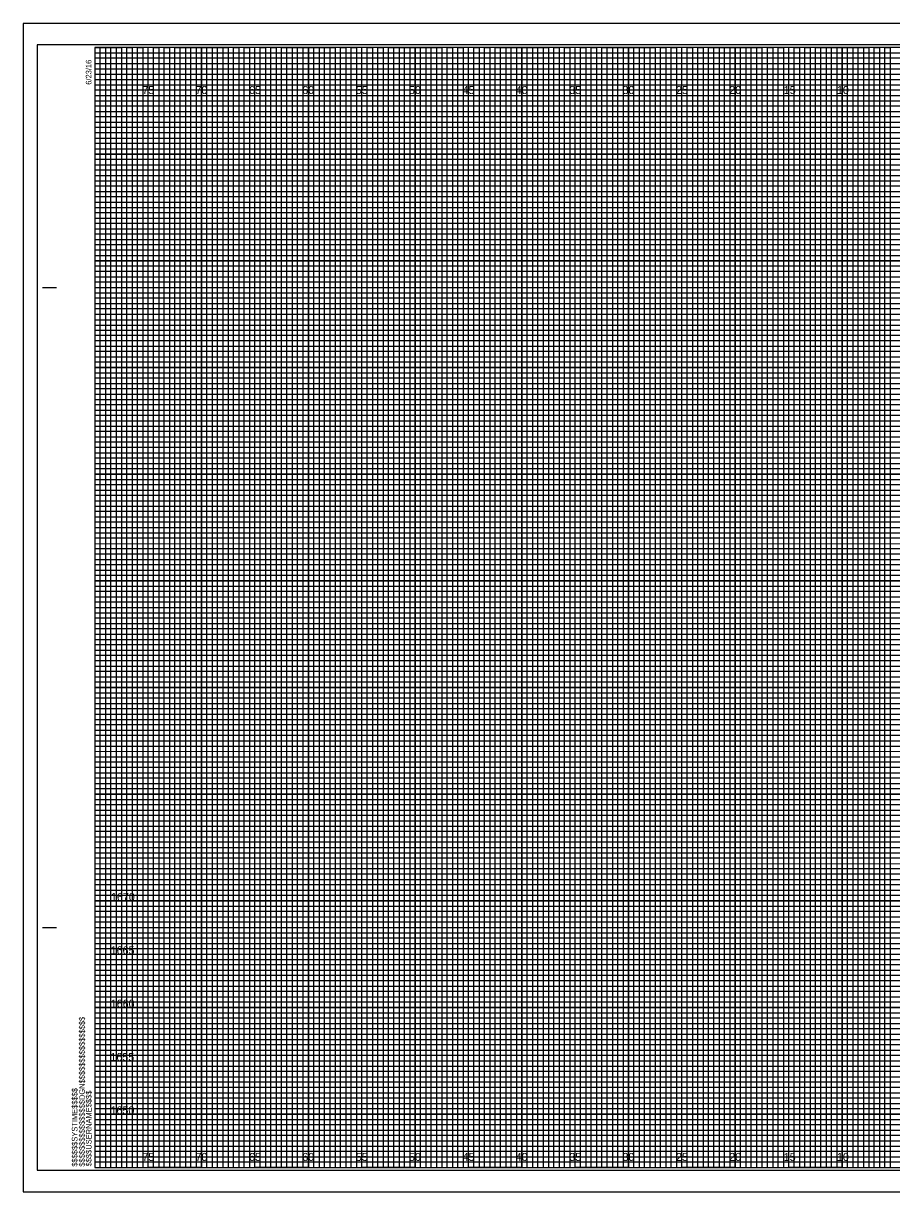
# Model space of a CAD drawing. Extents: x 224 to 392, y 1 to 330.
# Drawn here: x 223.6 to 304.9, y 221 to 330.5 of the extents above; entities that cross this region are included whole.
import ezdxf

# ---------------------------------------------------------------- set-up
doc = ezdxf.new("R2010")
doc.units = 0
for name, color, linetype in [('Prop Grid Mask', 7, 'Continuous'), ('Prop XS Elevation Labels', 7, 'Continuous'), ('Sheet Cross Section CELL', 7, 'Continuous'), ('Sheet Cross Section Grid Major CELL', 7, 'Continuous'), ('Sheet Cross Section Grid Middle CELL', 7, 'Continuous'), ('Sheet Cross Section Grid Minor 1 CELL', 7, 'Continuous'), ('Sheet Cross Section Grid Minor 2 CELL', 7, 'Continuous'), ('Sheet Cutting Line CELL', 7, 'Continuous'), ('Sheet DOT Grid CELL', 7, 'Continuous'), ('Sheet Plot Border Inside CELL', 7, 'Continuous'), ('Sheet Plot Border Outside CELL', 7, 'Continuous')]:
    doc.layers.add(name, color=color, linetype=linetype)

msp = doc.modelspace()

# ---------------------------------------------------------------- linework, layer by layer
at = {"layer": 'Sheet Cross Section CELL'}
for p, q in [((225.36, 305.71), (226.61, 305.71)), ((225.41, 305.71), (226.66, 305.71)), ((225.36, 245.71), (226.61, 245.71)), ((225.41, 245.71), (226.66, 245.71)), ((230.26, 223.21), (230.26, 223.21)), ((230.26, 223.21), (230.26, 223.21)), ((230.26, 223.21), (230.26, 223.21)), ((230.26, 223.21), (230.26, 223.21)), ((230.26, 223.21), (230.26, 223.21)), ((230.26, 223.21), (230.26, 223.21)), ((230.26, 223.21), (230.26, 223.21))]:
    msp.add_line(p, q, dxfattribs=at)
msp.add_lwpolyline([(390.26, 328.21), (230.26, 328.21), (230.26, 223.21), (390.26, 223.21)], close=True, dxfattribs=at)
at = {"layer": 'Sheet Cross Section Grid Major CELL'}
for p, q in [((235.26, 328.21), (230.26, 328.21)), ((235.26, 223.21), (235.26, 328.21)), ((245.26, 328.21), (240.26, 328.21)), ((240.26, 328.21), (240.26, 223.21)), ((245.26, 223.21), (245.26, 328.21)), ((255.26, 328.21), (250.26, 328.21)), ((250.26, 328.21), (250.26, 223.21)), ((255.26, 223.21), (255.26, 328.21)), ((265.26, 328.21), (260.26, 328.21)), ((260.26, 328.21), (260.26, 223.21)), ((265.26, 223.21), (265.26, 328.21)), ((275.26, 328.21), (270.26, 328.21)), ((270.26, 328.21), (270.26, 223.21)), ((275.26, 223.21), (275.26, 328.21)), ((285.26, 328.21), (280.26, 328.21)), ((280.26, 328.21), (280.26, 223.21)), ((285.26, 223.21), (285.26, 328.21)), ((295.26, 328.21), (290.26, 328.21)), ((290.26, 328.21), (290.26, 223.21)), ((295.26, 223.21), (295.26, 328.21)), ((305.26, 328.21), (300.26, 328.21)), ((300.26, 328.21), (300.26, 223.21)), ((240.26, 223.21), (235.26, 223.21)), ((250.26, 223.21), (245.26, 223.21)), ((260.26, 223.21), (255.26, 223.21)), ((270.26, 223.21), (265.26, 223.21)), ((280.26, 223.21), (275.26, 223.21)), ((290.26, 223.21), (285.26, 223.21)), ((300.26, 223.21), (295.26, 223.21))]:
    msp.add_line(p, q, dxfattribs=at)
for points in [[(230.26, 323.21), (390.26, 323.21), (390.26, 318.21), (230.26, 318.21)], [(230.26, 313.21), (390.26, 313.21), (390.26, 308.21), (230.26, 308.21)], [(230.26, 303.21), (390.26, 303.21), (390.26, 298.21), (230.26, 298.21)], [(230.26, 293.21), (390.26, 293.21), (390.26, 288.21), (230.26, 288.21)], [(230.26, 283.21), (390.26, 283.21), (390.26, 278.21), (230.26, 278.21)], [(230.26, 273.21), (390.26, 273.21), (390.26, 268.21), (230.26, 268.21)], [(230.26, 263.21), (390.26, 263.21), (390.26, 258.21), (230.26, 258.21)], [(230.26, 253.21), (390.26, 253.21), (390.26, 248.21), (230.26, 248.21)], [(230.26, 243.21), (390.26, 243.21), (390.26, 238.21), (230.26, 238.21)], [(230.26, 233.21), (390.26, 233.21), (390.26, 228.21), (230.26, 228.21)]]:
    msp.add_lwpolyline(points, dxfattribs=at)
at = {"layer": 'Sheet Cross Section Grid Middle CELL'}
for points in [[(230.26, 328.21), (232.76, 328.21), (232.76, 223.21), (237.76, 223.21), (237.76, 328.21), (242.76, 328.21), (242.76, 223.21), (247.76, 223.21), (247.76, 328.21), (252.76, 328.21), (252.76, 223.21), (257.76, 223.21), (257.76, 328.21), (262.76, 328.21), (262.76, 223.21), (267.76, 223.21), (267.76, 328.21), (272.76, 328.21), (272.76, 223.21), (277.76, 223.21), (277.76, 328.21), (282.76, 328.21), (282.76, 223.21), (287.76, 223.21), (287.76, 328.21), (292.76, 328.21), (292.76, 223.21), (297.76, 223.21), (297.76, 328.21), (302.76, 328.21), (302.76, 223.21), (307.76, 223.21)], [(230.26, 325.71), (367.76, 325.71)], [(230.26, 315.71), (390.26, 315.71), (390.26, 320.71), (230.26, 320.71)], [(230.26, 305.71), (390.26, 305.71), (390.26, 310.71), (230.26, 310.71)], [(230.26, 295.71), (390.26, 295.71), (390.26, 300.71), (230.26, 300.71)], [(230.26, 285.71), (390.26, 285.71), (390.26, 290.71), (230.26, 290.71)], [(230.26, 275.71), (390.26, 275.71), (390.26, 280.71), (230.26, 280.71)], [(230.26, 265.71), (390.26, 265.71), (390.26, 270.71), (230.26, 270.71)], [(230.26, 255.71), (390.26, 255.71), (390.26, 260.71), (230.26, 260.71)], [(230.26, 245.71), (390.26, 245.71), (390.26, 250.71), (230.26, 250.71)], [(230.26, 235.71), (390.26, 235.71), (390.26, 240.71), (230.26, 240.71)], [(230.26, 225.71), (390.26, 225.71), (390.26, 230.71), (230.26, 230.71)]]:
    msp.add_lwpolyline(points, dxfattribs=at)
at = {"layer": 'Sheet Cross Section Grid Minor 1 CELL'}
for p, q in [((230.26, 327.71), (360.26, 327.71)), ((360.26, 327.2), (230.26, 327.2)), ((230.26, 327.2), (230.26, 326.71)), ((230.26, 326.71), (360.26, 326.71)), ((360.26, 326.16), (230.26, 326.16)), ((230.26, 326.16), (230.26, 325.21)), ((230.26, 325.21), (390.26, 325.21))]:
    msp.add_line(p, q, dxfattribs=at)
for points in [[(230.26, 324.71), (365.26, 324.71), (390.26, 324.71), (390.26, 324.21), (230.26, 324.21)], [(230.26, 323.71), (390.26, 323.71), (390.26, 322.71), (230.26, 322.71)], [(230.26, 322.21), (390.26, 322.21), (390.26, 321.71), (230.26, 321.7)], [(230.26, 321.21), (390.26, 321.21), (390.26, 320.21), (230.26, 320.21)], [(230.26, 319.71), (390.26, 319.71), (390.26, 319.21), (230.26, 319.21)], [(230.26, 318.71), (390.26, 318.71), (390.26, 317.71), (230.26, 317.71)], [(230.26, 317.21), (390.26, 317.21), (390.26, 316.71), (230.26, 316.71)], [(230.26, 316.21), (390.26, 316.21), (390.26, 315.21), (230.26, 315.21)], [(230.26, 314.71), (390.26, 314.71), (390.26, 314.21), (230.26, 314.21)], [(230.26, 313.71), (390.26, 313.71), (390.26, 312.71), (230.26, 312.71)], [(230.26, 312.21), (390.26, 312.21), (390.26, 311.71), (230.26, 311.71)], [(230.26, 311.21), (390.26, 311.21), (390.26, 310.19), (390.26, 309.71), (390.26, 309.21), (230.26, 309.21)], [(230.26, 310.21), (390.26, 310.21), (390.26, 309.71), (230.26, 309.71)], [(230.26, 308.71), (390.26, 308.71), (390.26, 307.71), (230.26, 307.73)], [(230.26, 307.73), (390.26, 307.71), (390.26, 307.21), (230.26, 307.21)], [(230.26, 306.71), (390.26, 306.71), (390.26, 306.21), (230.26, 306.21)], [(230.26, 305.21), (390.26, 305.21), (390.26, 304.71), (230.26, 304.71)], [(230.26, 304.21), (390.26, 304.21), (390.26, 303.71), (230.26, 303.71)], [(230.23, 302.66), (390.26, 302.66), (390.26, 302.15), (230.23, 302.15)], [(230.26, 301.71), (390.26, 301.71), (390.26, 301.21), (230.26, 301.21)], [(230.26, 300.21), (390.26, 300.21), (390.26, 299.71), (230.26, 299.71)], [(230.26, 299.21), (390.26, 299.21), (390.26, 298.71), (230.26, 298.71)], [(230.26, 297.71), (390.26, 297.71), (390.26, 297.21), (230.26, 297.21)], [(230.26, 296.71), (390.26, 296.71), (390.26, 296.21), (230.26, 296.21)], [(230.26, 295.21), (390.26, 295.21), (390.26, 294.71), (230.26, 294.71)], [(230.26, 294.21), (390.26, 294.21), (390.26, 293.71), (230.26, 293.71)], [(230.26, 292.71), (390.26, 292.71), (390.26, 292.2), (230.26, 292.21)], [(230.26, 291.71), (390.26, 291.71), (390.26, 291.21), (230.26, 291.21)], [(230.26, 290.21), (390.26, 290.21), (390.26, 289.71), (230.26, 289.71)], [(230.26, 289.21), (390.26, 289.21), (390.26, 288.71), (230.26, 288.71)], [(230.26, 287.71), (390.26, 287.71), (390.26, 287.21), (230.26, 287.21)], [(230.26, 286.71), (390.26, 286.71), (390.26, 286.21), (230.26, 286.21)], [(230.26, 285.21), (390.26, 285.21), (390.26, 284.71), (230.26, 284.71)], [(230.26, 284.21), (390.26, 284.21), (390.26, 283.71), (230.26, 283.71)], [(230.26, 282.71), (390.26, 282.71), (390.26, 282.21), (230.26, 282.21)], [(230.26, 281.71), (390.3, 281.67), (390.26, 281.21), (230.26, 281.21)], [(230.26, 280.21), (390.26, 280.21), (390.26, 279.71), (230.26, 279.71)], [(230.26, 279.21), (390.26, 279.21), (390.26, 278.71), (230.26, 278.71)], [(230.26, 277.71), (390.26, 277.71), (390.26, 277.21), (230.26, 277.21)], [(230.26, 276.71), (390.26, 276.71), (390.26, 276.21), (230.26, 276.21)], [(230.26, 275.21), (390.26, 275.21), (390.26, 274.71), (230.26, 274.71)], [(230.26, 274.21), (390.26, 274.21), (390.26, 273.71), (230.26, 273.71)], [(230.26, 272.71), (390.26, 272.71), (390.26, 272.21), (230.26, 272.21)], [(230.26, 271.71), (390.26, 271.71), (390.26, 271.21), (230.26, 271.21)], [(230.26, 270.21), (390.26, 270.21), (390.26, 269.71), (230.26, 269.71)], [(230.26, 269.21), (390.26, 269.21), (390.26, 268.71), (230.26, 268.71)], [(230.26, 267.71), (390.26, 267.71), (390.26, 267.21), (230.26, 267.21)], [(230.26, 266.71), (390.26, 266.71), (390.26, 266.21), (230.26, 266.21)], [(230.26, 265.21), (390.26, 265.21), (390.26, 264.71), (230.26, 264.71)], [(230.26, 264.21), (390.26, 264.21), (390.26, 263.71), (230.26, 263.71)], [(230.26, 262.71), (390.26, 262.71), (390.26, 262.2), (230.26, 262.21)], [(230.26, 261.71), (390.26, 261.71), (390.26, 261.21), (230.26, 261.21)], [(230.26, 260.21), (390.26, 260.21), (390.26, 259.71), (230.26, 259.71)], [(230.26, 259.21), (390.26, 259.21), (390.26, 258.71), (230.26, 258.71)], [(230.26, 257.71), (390.26, 257.71), (390.26, 257.21), (230.26, 257.21)], [(230.26, 256.71), (390.26, 256.71), (390.26, 256.21), (230.26, 256.21)], [(230.26, 255.21), (390.26, 255.21), (390.26, 254.71), (230.26, 254.71)], [(230.26, 254.21), (390.26, 254.21), (390.26, 253.71), (230.26, 253.71)], [(230.26, 252.71), (390.26, 252.71), (390.26, 252.21), (230.26, 252.21)], [(230.26, 251.71), (390.3, 251.67), (390.26, 251.21), (230.26, 251.21)], [(230.26, 250.21), (390.26, 250.21), (390.26, 249.71), (230.26, 249.71)], [(230.26, 249.21), (390.26, 249.21), (390.26, 248.71), (230.26, 248.71)], [(230.26, 247.71), (390.26, 247.71), (390.26, 247.21), (230.26, 247.21)], [(230.26, 246.71), (390.26, 246.71), (390.26, 246.21), (230.26, 246.21)], [(230.26, 245.21), (390.26, 245.21), (390.26, 244.71), (230.26, 244.71)], [(230.26, 244.21), (390.26, 244.21), (390.26, 243.71), (230.26, 243.71)], [(230.26, 242.71), (390.26, 242.71), (390.26, 242.21), (230.26, 242.21)], [(230.26, 241.71), (390.26, 241.71), (390.26, 241.21), (230.26, 241.21)], [(230.26, 240.21), (390.26, 240.21), (390.26, 239.71), (230.26, 239.71)], [(230.26, 239.21), (390.26, 239.21), (390.26, 238.71), (230.26, 238.71)], [(230.26, 237.71), (390.26, 237.71), (390.26, 237.21), (230.26, 237.21)], [(230.26, 236.71), (390.26, 236.71), (390.26, 236.21), (230.26, 236.21)], [(230.26, 235.21), (390.26, 235.21), (390.26, 234.71), (230.26, 234.71)], [(230.26, 234.21), (390.26, 234.21), (390.26, 233.71), (230.26, 233.71)], [(230.26, 232.71), (390.26, 232.71), (390.26, 232.21), (230.26, 232.21)], [(230.26, 231.71), (390.26, 231.71), (390.26, 231.21), (230.26, 231.21)], [(230.26, 230.21), (390.26, 230.21), (390.26, 229.71), (230.26, 229.71)], [(230.26, 229.21), (390.26, 229.21), (390.26, 228.71), (230.26, 228.71)], [(230.26, 227.71), (390.26, 227.71), (390.26, 227.21), (230.26, 227.21)], [(230.26, 226.71), (390.26, 226.71), (390.26, 226.21), (230.26, 226.21)], [(230.26, 225.21), (390.26, 225.21), (390.26, 224.71), (230.26, 224.71)], [(230.26, 224.21), (390.26, 224.21), (390.26, 223.71), (230.26, 223.71)]]:
    msp.add_lwpolyline(points, dxfattribs=at)
at = {"layer": 'Sheet Cross Section Grid Minor 2 CELL'}
for points in [[(230.26, 223.21), (230.76, 223.21), (230.76, 328.21), (231.26, 328.21), (231.26, 223.21)], [(231.26, 223.21), (231.76, 223.21), (231.76, 328.21), (232.26, 328.21), (232.26, 223.21)], [(232.76, 223.21), (233.26, 223.21), (233.26, 328.21), (233.76, 328.21), (233.76, 223.21)], [(233.76, 223.21), (234.26, 223.21), (234.26, 328.21), (234.76, 328.21), (234.76, 223.21)], [(235.26, 223.21), (235.76, 223.21), (235.76, 328.21), (236.26, 328.21), (236.26, 223.21)], [(236.26, 223.21), (236.76, 223.21), (236.76, 328.21), (237.26, 328.21), (237.26, 223.21)], [(237.76, 223.21), (238.26, 223.21), (238.26, 328.21), (238.76, 328.21), (238.76, 223.21)], [(238.76, 223.21), (239.26, 223.21), (239.26, 328.21), (239.76, 328.21), (239.76, 223.21)], [(240.26, 223.21), (240.76, 223.21), (240.76, 328.21), (241.26, 328.21), (241.26, 223.21)], [(241.26, 223.21), (241.76, 223.21), (241.76, 328.21), (242.26, 328.21), (242.26, 223.21)], [(242.76, 223.21), (243.26, 223.21), (243.26, 328.21), (243.76, 328.21), (243.76, 223.21)], [(243.76, 223.21), (244.26, 223.21), (244.26, 328.21), (244.76, 328.21), (244.76, 223.21)], [(245.26, 223.21), (245.76, 223.21), (245.76, 328.21), (246.26, 328.21), (246.26, 223.21)], [(246.26, 223.21), (246.76, 223.21), (246.76, 328.21), (247.26, 328.21), (247.26, 223.21)], [(247.76, 223.21), (248.26, 223.21), (248.26, 328.21), (248.76, 328.21), (248.76, 223.21)], [(248.76, 223.21), (249.26, 223.21), (249.26, 328.21), (249.76, 328.21), (249.76, 223.21)], [(250.26, 223.21), (250.76, 223.21), (250.76, 328.21), (251.26, 328.21), (251.26, 223.21)], [(251.26, 223.21), (251.76, 223.21), (251.76, 328.21), (252.26, 328.21), (252.26, 223.21)], [(252.76, 223.21), (253.26, 223.21), (253.26, 328.21), (253.76, 328.21), (253.76, 223.21)], [(253.76, 223.21), (254.26, 223.21), (254.26, 328.21), (254.76, 328.21), (254.76, 223.21)], [(255.26, 223.21), (255.76, 223.21), (255.76, 328.21), (256.26, 328.21), (256.26, 223.21)], [(256.26, 223.21), (256.76, 223.21), (256.76, 328.21), (257.26, 328.21), (257.26, 223.21)], [(257.76, 223.21), (258.26, 223.21), (258.26, 328.21), (258.76, 328.21), (258.76, 223.21)], [(258.76, 223.21), (259.26, 223.21), (259.26, 328.21), (259.76, 328.21), (259.76, 223.21)], [(260.26, 223.21), (260.76, 223.21), (260.76, 328.21), (261.26, 328.21), (261.26, 223.21)], [(261.26, 223.21), (261.76, 223.21), (261.76, 328.21), (262.26, 328.21), (262.26, 223.21)], [(262.76, 223.21), (263.26, 223.21), (263.26, 328.21), (263.76, 328.21), (263.76, 223.21)], [(263.76, 223.21), (264.26, 223.21), (264.26, 328.21), (264.76, 328.21), (264.76, 223.21)], [(265.26, 223.21), (265.76, 223.21), (265.76, 328.21), (266.26, 328.21), (266.26, 223.21)], [(266.26, 223.21), (266.76, 223.21), (266.76, 328.21), (267.26, 328.21), (267.26, 223.21)], [(267.76, 223.21), (268.26, 223.21), (268.26, 328.21), (268.76, 328.21), (268.76, 223.21)], [(268.76, 223.21), (269.26, 223.21), (269.26, 328.21), (269.76, 328.21), (269.76, 223.21)], [(270.26, 223.21), (270.76, 223.21), (270.76, 328.21), (271.26, 328.21), (271.26, 223.21)], [(271.26, 223.21), (271.76, 223.21), (271.76, 328.21), (272.26, 328.21), (272.26, 223.21)], [(272.76, 223.21), (273.26, 223.21), (273.26, 328.21), (273.76, 328.21), (273.76, 223.21)], [(273.76, 223.21), (274.26, 223.21), (274.26, 328.21), (274.76, 328.21), (274.76, 223.21)], [(275.26, 223.21), (275.76, 223.21), (275.76, 328.21), (276.26, 328.21), (276.26, 223.21)], [(276.26, 223.21), (276.76, 223.21), (276.76, 328.21), (277.26, 328.21), (277.26, 223.21)], [(277.76, 223.21), (278.26, 223.21), (278.26, 328.21), (278.76, 328.21), (278.76, 223.21)], [(278.76, 223.21), (279.26, 223.21), (279.26, 328.21), (279.76, 328.21), (279.76, 223.21)], [(280.26, 223.21), (280.76, 223.21), (280.76, 328.21), (281.26, 328.21), (281.26, 223.21)], [(281.26, 223.21), (281.76, 223.21), (281.76, 328.21), (282.26, 328.21), (282.26, 223.21)], [(282.76, 223.21), (283.26, 223.21), (283.26, 328.21), (283.76, 328.21), (283.76, 223.21)], [(283.76, 223.21), (284.26, 223.21), (284.26, 328.21), (284.76, 328.21), (284.76, 223.21)], [(285.26, 223.21), (285.76, 223.21), (285.76, 328.21), (286.26, 328.21), (286.26, 223.21)], [(286.26, 223.21), (286.76, 223.21), (286.76, 328.21), (287.26, 328.21), (287.26, 223.21)], [(287.76, 223.21), (288.26, 223.21), (288.26, 328.21), (288.76, 328.21), (288.76, 223.21)], [(288.76, 223.21), (289.26, 223.21), (289.26, 328.21), (289.76, 328.21), (289.76, 223.21)], [(290.26, 223.21), (290.76, 223.21), (290.76, 328.21), (291.26, 328.21), (291.26, 223.21)], [(291.26, 223.21), (291.76, 223.21), (291.76, 328.21), (292.26, 328.21), (292.26, 223.21)], [(292.76, 223.21), (293.26, 223.21), (293.26, 328.21), (293.76, 328.21), (293.76, 223.21)], [(293.76, 223.21), (294.26, 223.21), (294.26, 328.21), (294.76, 328.21), (294.76, 223.21)], [(295.26, 223.21), (295.76, 223.21), (295.76, 328.21), (296.26, 328.21), (296.26, 223.21)], [(296.26, 223.21), (296.76, 223.21), (296.76, 328.21), (297.26, 328.21), (297.26, 223.21)], [(297.76, 223.21), (298.26, 223.21), (298.26, 328.21), (298.76, 328.21), (298.76, 223.21)], [(298.76, 223.21), (299.26, 223.21), (299.26, 328.21), (299.76, 328.21), (299.76, 223.21)], [(300.26, 223.21), (300.76, 223.21), (300.76, 328.21), (301.26, 328.21), (301.26, 223.21)], [(301.26, 223.21), (301.76, 223.21), (301.76, 328.21), (302.26, 328.21), (302.26, 223.21)], [(302.76, 223.21), (303.26, 223.21), (303.26, 328.21), (303.76, 328.21), (303.76, 223.21)], [(303.76, 223.21), (304.26, 223.21), (304.26, 328.21), (304.76, 328.21), (304.76, 223.21)]]:
    msp.add_lwpolyline(points, dxfattribs=at)
at = {"layer": 'Sheet Cutting Line CELL'}
for p, q in [((391.91, 330.46), (223.56, 330.46)), ((223.56, 330.46), (223.56, 220.96)), ((223.56, 220.96), (391.91, 220.96))]:
    msp.add_line(p, q, dxfattribs=at)
at = {"layer": 'Sheet DOT Grid CELL'}
for p, q in [((235.26, 223.21), (235.26, 328.21)), ((240.26, 223.21), (240.26, 328.21)), ((245.26, 223.21), (245.26, 328.21)), ((250.26, 223.21), (250.26, 328.21)), ((255.26, 223.21), (255.26, 328.21)), ((260.26, 223.21), (260.26, 328.21)), ((265.26, 223.21), (265.26, 328.21)), ((270.26, 223.21), (270.26, 328.21)), ((275.26, 223.21), (275.26, 328.21)), ((280.26, 223.21), (280.26, 328.21)), ((285.26, 223.21), (285.26, 328.21)), ((290.26, 223.21), (290.26, 328.21)), ((295.26, 223.21), (295.26, 328.21)), ((300.26, 223.21), (300.26, 328.21)), ((230.26, 323.21), (390.26, 323.21)), ((230.26, 318.21), (390.26, 318.21)), ((230.26, 313.21), (390.26, 313.21)), ((230.26, 308.21), (390.26, 308.21)), ((230.26, 303.21), (390.26, 303.21)), ((230.26, 298.21), (390.26, 298.21)), ((230.26, 293.21), (390.26, 293.21)), ((230.26, 288.21), (390.26, 288.21)), ((230.26, 283.21), (390.26, 283.21)), ((230.26, 278.21), (390.26, 278.21)), ((230.26, 273.21), (390.26, 273.21)), ((230.26, 268.21), (390.26, 268.21)), ((230.26, 263.21), (390.26, 263.21)), ((230.26, 258.21), (390.26, 258.21)), ((230.26, 253.21), (390.26, 253.21)), ((230.26, 248.21), (390.26, 248.21)), ((230.26, 243.21), (390.26, 243.21)), ((230.26, 238.21), (390.26, 238.21)), ((230.26, 233.21), (390.26, 233.21)), ((230.26, 228.21), (390.26, 228.21))]:
    msp.add_line(p, q, dxfattribs=at)
at = {"layer": 'Sheet Plot Border Inside CELL'}
msp.add_lwpolyline([(224.86, 222.96), (391.46, 222.96), (391.46, 328.46), (224.86, 328.46)], close=True, dxfattribs=at)
at = {"layer": 'Sheet Plot Border Outside CELL'}
msp.add_lwpolyline([(223.56, 220.96), (391.91, 220.96), (391.91, 330.46), (223.56, 330.46)], close=True, dxfattribs=at)

# ---------------------------------------------------------------- texts
at = {"layer": 'Prop Grid Mask'}
for s, p in [('75', (234.71, 323.84)), ('70', (239.69, 323.84)), ('65', (244.71, 323.84)), ('60', (249.69, 323.84)), ('55', (254.71, 323.84)), ('50', (259.69, 323.84)), ('45', (264.71, 323.84)), ('40', (269.69, 323.84)), ('35', (274.71, 323.84)), ('30', (279.69, 323.84)), ('25', (284.71, 323.84)), ('20', (289.69, 323.84)), ('15', (294.8, 323.84)), ('10', (299.78, 323.84)), ('75', (234.71, 223.84)), ('70', (239.69, 223.84)), ('65', (244.71, 223.84)), ('60', (249.69, 223.84)), ('55', (254.71, 223.84)), ('50', (259.69, 223.84)), ('45', (264.71, 223.84)), ('40', (269.69, 223.84)), ('35', (274.71, 223.84)), ('30', (279.69, 223.84)), ('25', (284.71, 223.84)), ('20', (289.69, 223.84)), ('15', (294.8, 223.84)), ('10', (299.78, 223.84))]:
    msp.add_text(s, height=0.75, dxfattribs=at).set_placement(p)
at = {"layer": 'Prop XS Elevation Labels'}
for s, p in [('1670', (231.77, 248.21)), ('1665', (231.74, 243.21)), ('1660', (231.75, 238.21)), ('1655', (231.72, 233.21)), ('1650', (231.73, 228.21))]:
    msp.add_text(s, height=0.75, dxfattribs=at).set_placement(p)
at = {"layer": 'Sheet Cross Section CELL'}
for s, p in [('6/23/16', (229.94, 324.71)), ('$$$$$$$$$$$$$$$$DGN$$$$$$$$$$$$$$$$', (229.32, 223.3)), ('$$$$$$SYSTIME$$$$$', (228.63, 223.3)), ('$$$$USERNAME$$$$', (229.95, 223.33))]:
    msp.add_text(s, height=0.525, rotation=90, dxfattribs=at).set_placement(p)

doc.saveas('drawing.dxf')
